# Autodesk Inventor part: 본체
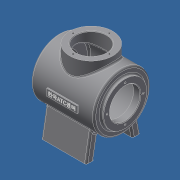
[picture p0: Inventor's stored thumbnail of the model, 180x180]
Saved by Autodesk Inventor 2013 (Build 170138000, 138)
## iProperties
Created: 2015-01
Part Number: 본체
Material: Generic
Document SubType Name: Modeling
Designer: kb146
Density: 1 g/cm^3
Mass: 376.8 g
Surface Area: 1060.37 cm^2
Volume: 376.8 cm^3
Author: kb146
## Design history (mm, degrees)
sketch "스케치1"
  geometry: L1 (-61, 0)-(61, 0); L2 (-61, 27)-(-49, 27); L3 (-49, 27)-(-49, 45); L4 (-49, 45)-(48, 45); L5 (48, 45)-(48, 27); L6 (48, 27)-(61, 27); L7 (61, 27)-(61, 38); L8 (61, 38)-(56, 38); L9 (56, 38)-(56, 50); L10 (56, 50)-(-56, 50); L11 (-56, 50)-(-56, 38); L12 (-56, 38)-(-61, 38); L13 (-61, 38)-(-61, 27); 2 further points
  constraints: 26 end point, 10 parallel, 3 collinear, 2 vertical alignment, 1 coincident, 1 horizontal, 1 midpoint, 1 perpendicular
  dimensions: "d0" = 54 diameter of L6 L1; "d2" = 76 diameter of L8 L1; "d3" = 100 diameter of L10 L1; "d4" = 90 diameter of L4 L1; "d5" = 97 distance of L3.end L4.end; "d6" = 122 distance of L1.start L1.end; "d7" = 12 distance of L2.start L2.end; "d8" = 5 distance of L11.end L12.end; "d9" = 5 distance of L7.end L8.end
revolve "회전1" sketch "스케치1" stored, may be unused: angle "d10" = 90 deg
sketch "스케치2"
  geometry: L1 (-48, -80)-(-34, -80); L2 (-34, -80)-(-27.282, -41.901); L3 (-48, -80)-(-39.336, -30.865); A1 r 50 centre (0, 0) between (-27.282, -41.901) and (-39.336, -30.865) reference; 1 further point
  constraints: 6 end point, 2 point on circle, 1 horizontal
  dimensions: "d12" = 80 deg angle of L1 L2; "d13" = 100 deg angle of L3 L1; "d14" = 80 distance from line of point (0, 0) L1; "d15" = 48 horizontal distance of point (0, 0) L1.start; "d16" = 14 distance of L1.start L1.end
extrude "돌출1" join sketch "스케치2" stored distance "d17" = 80; taper "d18" = 0 deg
node "작업 평면3"
sketch "스케치5"
  geometry: C1 r 27 at (0, 0) reference; 1 further point
  constraints: 1 horizontal alignment
  dimensions: "d26" = 32 distance of point (32, 0) C1.centre
hole "구멍1" sketch "스케치5" at (32, 0) diameter "d27" = 3.242; stored, may be unused: countersink angle "d31" = 90 deg, drill point angle "d33" = 118 deg; dims "d28" = 8, "d29" = 4, "d30" = 2, "d32" = 10
node "작업 평면4"
sketch "스케치9"
  geometry: L1 (-61, 38)-(-61, -38) reference; C1 r 38 at (1, 0); 1 further point
  constraints: 1 centre point, 1 horizontal alignment
  dimensions: "d38" = 76 diameter of C1; "d39" = 62 distance from line of C1.centre L1
extrude "돌출4" join sketch "스케치9" stored distance "d40" = 80; taper "d41" = 0 deg
sketch "스케치11"
  geometry: C1 r 38 at (0, 0) reference; C2 r 27 at (0, 0)
  constraints: 1 centre point, 1 coincident
  dimensions: "d42" = 54 diameter of C2
extrude "돌출5" cut sketch "스케치11" stored distance "d43" = 80; taper "d44" = 0 deg
node "작업 평면8"
sketch "스케치16"
  geometry: L1 (28, -6)-(-26, -6); L2 (-26, -6)-(-26, 6); L3 (-26, 6)-(28, 6); L4 (28, 6)-(28, -6); L5 (28, -6)-(-26, 6); L6 (-26, -6)-(28, 6); L7 (-61, 38)-(-61, -38) reference; 4 further points
  constraints: 12 end point, 4 midpoint, 2 parallel, 1 horizontal, 1 horizontal alignment, 1 perpendicular
  dimensions: "d66" = 54 distance of L2.end L3.end; "d68" = 12 distance of L3.end L1.start; "d69" = 62 distance from line of point (1, 0) L7
extrude "돌출6" join sketch "스케치16" stored distance "d70" = 80; taper "d71" = 0 deg
sketch "스케치17"
  geometry: L1 (-61, 38)-(-61, -38) reference; 3 further points
  constraints: 1 horizontal alignment, 1 midpoint, 1 other
  dimensions: "d72" = 62 distance from line of point (1, 0) L1
feature "엠보싱3" sketch "스케치17" dims "d16" = 14, "d73" = 0.5, "d74" = 0
sketch "스케치18"
  geometry: C1 r 27 at (0, 0) reference; 1 further point
  constraints: 1 vertical alignment
  dimensions: "d75" = 32 distance of point (0, 32) C1.centre
hole "구멍2" sketch "스케치18" at (0, 32) diameter "d76" = 3.242; stored, may be unused: countersink angle "d80" = 90 deg, drill point angle "d82" = 118 deg; dims "d77" = 8, "d78" = 4, "d79" = 2, "d81" = 10
chamfer "모따기1" distance "d86" = 1; stored, may be unused: second distance "d87" = 2, angle "d88" = 45 deg
fillet "모깎기1" dims "d89" = 3
fillet "모깎기2" dims "d90" = 3
fillet "모깎기3" dims "d91" = 3
node "솔리드1"
mirror "대칭1"
pattern_circular "원형 패턴1" dims angle "d35" = 360 deg
mirror "대칭2"
pattern_circular "원형 패턴2" dims angle "d84" = 360 deg
other parameters: "d19" = 62, "d37" = 62, "d65" = -52
